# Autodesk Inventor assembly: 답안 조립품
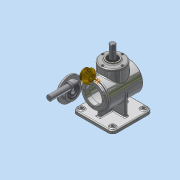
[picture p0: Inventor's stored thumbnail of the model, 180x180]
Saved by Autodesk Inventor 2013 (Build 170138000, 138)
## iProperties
Created: 2015-07
Part Number: 답안 조립품
Document SubType Name: Assembly
Designer: dgall
Author: dgall
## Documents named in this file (13)
- C:\Users\dgall\Desktop\450705V1012\답안 조립품.iam
- C:\Users\dgall\Desktop\450705V1012\본체.ipt
- C:\Users\dgall\Desktop\450705V1012\커버.ipt
- C:\Users\dgall\Desktop\450705V1012\메인 축.ipt
- 메인 축.ipt
- C:\Users\dgall\Desktop\450705V1012\오일실.ipt
- C:\Users\dgall\Desktop\450705V1012\키 5x5.ipt
- C:\Users\dgall\Desktop\450705V1012\메인 베벨기어.ipt
- C:\Users\dgall\Desktop\450705V1012\베어링 6203.ipt
- C:\Users\dgall\Desktop\450705V1012\서브 축.ipt
- 서브 축.ipt
- C:\Users\dgall\Desktop\450705V1012\서브 베벨기어.ipt
- C:\Users\dgall\Desktop\450705V1012\키 4x4.ipt
